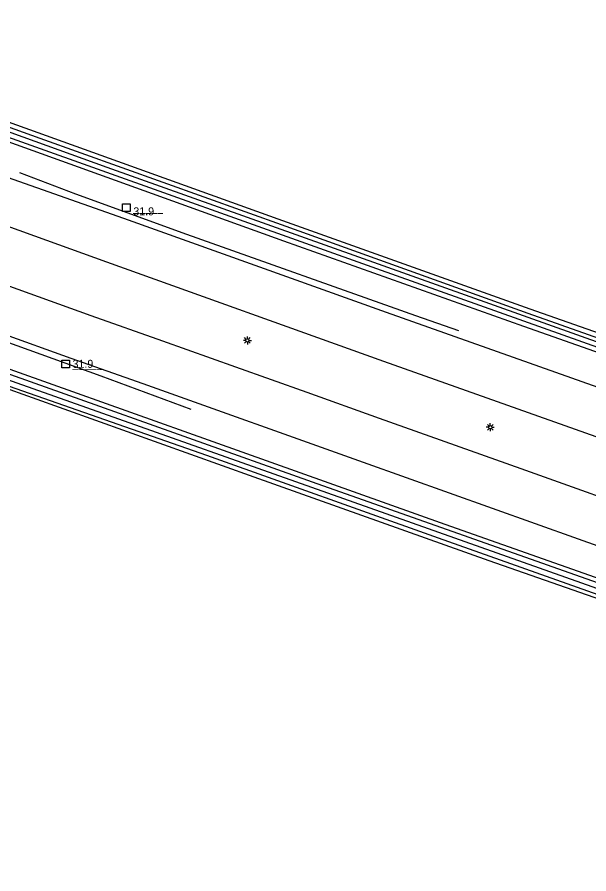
# Model space of a CAD drawing. Extents: x 130998 to 133001, y 398999 to 403002.
# Drawn here: x 131374.3 to 131463.7, y 400660.4 to 400794.2 of the extents above; entities that cross this region are included whole.
import ezdxf

# ---------------------------------------------------------------- set-up
doc = ezdxf.new("R2010")
doc.units = 0
for name, color, linetype in [('gg-afsc-hekwerk', 7, 'Continuous'), ('gg-knt-verharding', 7, 'Continuous'), ('gg-kntw-bovenkant insteek waterloop', 7, 'Continuous'), ('gg-kntw-waterlijn', 7, 'Continuous'), ('gt-anno-nummer hm paal', 7, 'Continuous'), ('gt-knt-geleideconstructie', 7, 'Continuous'), ('gt-symb-hm paal', 7, 'Continuous'), ('gt-symb-lichtmast', 7, 'Continuous')]:
    doc.layers.add(name, color=color, linetype=linetype)

# ---------------------------------------------------------------- blocks, each defined once
blk = doc.blocks.new('gt0-HMpaal')
at = {"layer": 'gt-symb-hm paal'}
blk.add_lwpolyline([(-0.6, 0.6), (0.6, 0.6), (0.6, -0.6), (-0.6, -0.6)], close=True, dxfattribs=at)
blk = doc.blocks.new('gt0-LMAST')
at = {"layer": 'gt-symb-lichtmast'}
for p, q in [((-0.18, 0.17), (-0.45, 0.44)), ((-0.01, 0.25), (-0.01, 0.62)), ((0.17, 0.17), (0.44, 0.44)), ((-0.26, 0), (-0.63, 0)), ((-0.18, -0.18), (-0.45, -0.45)), ((-0.01, -0.25), (-0.01, -0.63)), ((0.44, -0.45), (0.17, -0.18)), ((0.24, 0), (0.62, 0))]:
    blk.add_line(p, q, dxfattribs=at)
blk.add_circle((-0.01, 0), 0.25, dxfattribs=at)

msp = doc.modelspace()

# ---------------------------------------------------------------- linework, layer by layer
at = {"layer": 'gg-afsc-hekwerk'}
for points in [[(131497.8, 400733.38), (131454.49, 400748.61), (131415.06, 400762.67), (131365.66, 400780.43)], [(131593.98, 400660.04), (131575.4, 400665.62), (131555.28, 400671.96), (131501.61, 400690.6), (131448.09, 400709.3), (131411.32, 400722.36), (131371.75, 400736.54), (131359.41, 400740.98)]]:
    msp.add_lwpolyline(points, dxfattribs=at)
at = {"layer": 'gg-knt-verharding'}
for points in [[(131607.69, 400688.26), (131603.56, 400689.48), (131591.6, 400693.13), (131579.39, 400696.95), (131564.83, 400701.63), (131549.81, 400706.58), (131484.96, 400729.32), (131432, 400748.11), (131390.98, 400762.76), (131370.98, 400769.82)], [(131363.26, 400764.99), (131388.24, 400755.99), (131431.57, 400740.48), (131482.5, 400722.42), (131532.7, 400704.75), (131543.9, 400700.93), (131555.06, 400697.19), (131566.17, 400693.56), (131577.23, 400690.02), (131589.03, 400686.33), (131600.78, 400682.76), (131606.45, 400681.07)], [(131604.9, 400672.51), (131600.89, 400673.68), (131589.64, 400677), (131578.29, 400680.47), (131566.05, 400684.41), (131555.1, 400688.04), (131543.57, 400691.95), (131520.86, 400699.71), (131498.69, 400707.44), (131487.06, 400711.58), (131475.54, 400715.65), (131453.05, 400723.64), (131430.91, 400731.54), (131419.63, 400735.59), (131408.45, 400739.53), (131397.08, 400743.6), (131385.87, 400747.58), (131361.66, 400756.25)], [(131360.64, 400748.84), (131382.7, 400740.94), (131393.92, 400736.99), (131428.36, 400724.68), (131461.96, 400712.72), (131472.81, 400708.89), (131483.34, 400705.15), (131506.81, 400696.88), (131518.15, 400692.92), (131540.06, 400685.42), (131551.47, 400681.54), (131564.21, 400677.3), (131574.99, 400673.8), (131586.51, 400670.3), (131598.8, 400666.63), (131603.43, 400665.31)]]:
    msp.add_lwpolyline(points, dxfattribs=at)
at = {"layer": 'gg-kntw-bovenkant insteek waterloop'}
for points in [[(131609.01, 400695.52), (131606.48, 400696.26), (131579.05, 400704.6), (131543.68, 400716.38), (131527.99, 400721.84), (131454.18, 400747.93), (131416.32, 400761.53), (131377.89, 400775.27), (131365.54, 400779.72)], [(131608.68, 400693.37), (131605.79, 400694.21), (131578.56, 400702.72), (131542.97, 400714.5), (131489.41, 400733.23), (131453.49, 400745.9), (131415.99, 400759.23), (131365.18, 400777.49)], [(131359.93, 400743.94), (131366.21, 400741.66), (131404.87, 400727.94), (131441.15, 400715.01), (131494.31, 400696.29), (131526.53, 400684.88), (131553.8, 400675.7), (131577.86, 400668.19)], [(131577.34, 400665.98), (131553.07, 400673.4), (131525.44, 400682.81), (131493.28, 400693.97), (131440.15, 400712.84), (131403.93, 400725.75), (131365.59, 400739.14), (131359.46, 400741.36)]]:
    msp.add_lwpolyline(points, dxfattribs=at)
at = {"layer": 'gg-kntw-waterlijn'}
for points in [[(131323.23, 400794.23), (131336.29, 400789.52), (131388.32, 400770.77), (131466.26, 400743.05), (131546.12, 400715.03), (131577.55, 400704.69), (131608.99, 400694.92), (131641.83, 400685.4), (131670.95, 400677.74), (131671.03, 400677.32), (131670.44, 400677.05), (131665.55, 400678.29), (131626.05, 400688.99), (131595.43, 400698.12), (131572.62, 400705.33), (131529.22, 400719.96), (131491.83, 400733.07), (131430.49, 400754.92), (131322.38, 400793.43), (131323.23, 400794.23)], [(131312.23, 400760.48), (131362.36, 400742.24), (131420.42, 400721.61), (131529.71, 400683.05), (131557.24, 400673.61), (131597.27, 400661.54), (131597.03, 400660.72), (131589.79, 400662.79), (131552.11, 400674.44), (131490.64, 400695.87), (131422.83, 400719.85), (131347.44, 400746.52), (131312.08, 400759.51), (131312.23, 400760.48)]]:
    msp.add_lwpolyline(points, dxfattribs=at)
at = {"layer": 'gt-knt-geleideconstructie'}
for points in [[(131443.32, 400745.23), (131436.58, 400747.54), (131400.8, 400760.29), (131383.47, 400766.59), (131374.72, 400769.89)], [(131332.47, 400757.73), (131343.44, 400753.93), (131354.7, 400749.89), (131364.8, 400746.33), (131387.39, 400738.18), (131401.42, 400732.99)]]:
    msp.add_lwpolyline(points, dxfattribs=at)

# ---------------------------------------------------------------- block references
at = {"layer": 'gt-symb-hm paal'}
for p in [(131391.36, 400764.46), (131381.86, 400740.04)]:
    msp.add_blockref('gt0-HMpaal', p, dxfattribs=at)
at = {"layer": 'gt-symb-lichtmast'}
for p in [(131410.28, 400743.72), (131448.24, 400730.16)]:
    msp.add_blockref('gt0-LMAST', p, dxfattribs=at)

# ---------------------------------------------------------------- texts
at = {"layer": 'gt-anno-nummer hm paal'}
for p in [(131392.44, 400763.26), (131382.94, 400739.44)]:
    msp.add_text('31.9', height=1.25, dxfattribs=at).set_placement(p)
at = {"layer": 'gt-symb-hm paal'}
for p in [(131392.44, 400763.86), (131382.94, 400739.44)]:
    msp.add_text('_____', height=1.25, dxfattribs=at).set_placement(p)

doc.saveas('drawing.dxf')
